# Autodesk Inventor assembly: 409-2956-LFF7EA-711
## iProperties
Created: 2010-06
Part Number: 409-2956-LFF7EA-711
Document SubType Name: Weldment
Designer: S. Boerckel
Mass: 16468.2 g
Surface Area: 4749.52 cm^2
Volume: 2096.13 cm^3
Density: 7.85648 g/cm^3
Description: PUMP INLET
Weld Material: Welded Steel Mild
User Status: WELD
Material: WELDMENT
SMR: =<MATERIAL>
Author: S. Boerckel
Revision Number: A
Subject: DEMIN WATER FORWARDING PUMP SKID-7EA
